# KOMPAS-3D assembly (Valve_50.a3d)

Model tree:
1. Plane XY
2. Plane ZX
3. Plane ZY
4. X Axis
5. Y Axis
6. Z Axis
7. Origin
8. Control point:1
9. Attachment Point:1
10. Attachment Point:2  (labels: C:\Program Files\ASCON\KOMPAS-3D V10\Sys\graphic.lyt)

Referenced files in C:\Program Files\ASCON\KOMPAS-3D V10\Libs\Piping\Models\Tanks\: Piping_Valve_50_1000.m3d, Piping_Joint_50_1000.m3d, Piping_Flange_50_1000.m3d
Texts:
  Valve Dn 50
  Steel ASTM A295
  Three Point Plane
  Plane at Angle
  Line and Point Plane
  Axis through Two Vertices
  Axis of Feature
  Axis of Conical Surface
  Axis through Edge
  Trim by Surface
  Trim by Sketch
  Intersection Axis of Two Planes
  Two Line Plane
  Line and Face Plane
  Pattern by Sample
  Point in CM
  Feature with No History
  Linear Dimension from Line to Point
  Surface Finish Symbol
  Geometric Tolerance Symbol
  Текст на чертеже
  Линия-выноска #1
  Линия-выноска #2
  Линия-выноска #3
  Отклонения формы и база
  Марка координационной оси
  Марка/позиционное обозначение с линией-выноской
  Марка/позиционное обозначение на линии
  Марка/позиционное обозначение без линии-выноски
  Прокладка Dy 50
